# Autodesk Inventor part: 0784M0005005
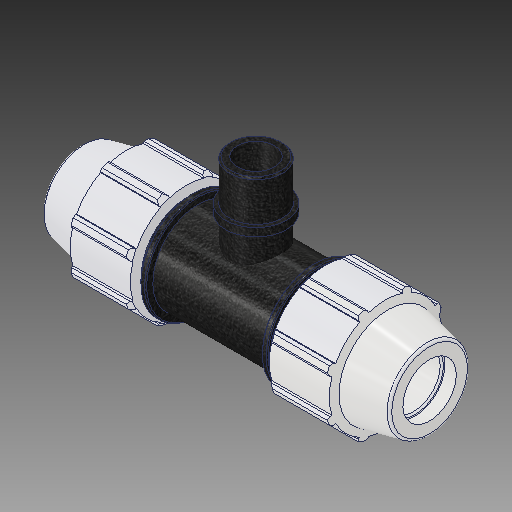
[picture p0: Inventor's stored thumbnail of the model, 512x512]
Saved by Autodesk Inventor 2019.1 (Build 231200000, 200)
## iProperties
Created: 2017-02
Part Number: 0784M0005005
Material: PVC-Piping
Description: PLASSON TEE WITH THREADED MALE OFFTAKE 1/2'' - 1/2''M - 1/2''
Document SubType Name: Modeling
Designer: KIM
Mass: 92.6774 g
Surface Area: 199.44 cm^2
Volume: 66.1981 cm^3
Density: 1.4 g/cm^3
Appearance: PTFE
Author: Кирилл
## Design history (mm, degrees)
derived "0784M0.ipt"
feature "Solid1::0784M0.ipt"
feature "Solid2::0784M0.ipt"
tag "TaggingFeature1"
body "Solid1"
body "Solid2"
other parameters: "d2" = 21.2, "d4" = 5.74675, "d5" = 16.55064, "d7" = 48.006, "d11" = 2.2987, "d13" = 120 deg, "d14" = 31.8, "d15" = 12 deg, "d16" = 41.76522, "d18" = 1.06, "d19" = 35 deg, "d20" = 17.5 deg, "d21" = 44.64558, "d23" = 0, "d25" = 360 deg, "d27" = 0.96012, "d33" = 0.424, "d42" = 24.82596, "d43" = 1.44018, "d46" = 0.636, "d68" = 2.2987, "d72" = 45.974, "d73" = 20.955, "d74" = 16.002, "d75" = 24.09825, "d76" = 14.6685, "d77" = 19.2024, "d80" = 0.62865, "d91" = 36.0045, "d93" = 57.912, "d95" = 19.08, "d99" = 137.922, "d101" = 0, "d103" = 0, "d105" = 0, "d_" = 21.2, "E_" = 48.006, "A_" = 45.974, "l_" = 57.912, "l_2" = 16.002, "H_" = 137.922, "G_" = 20.955
